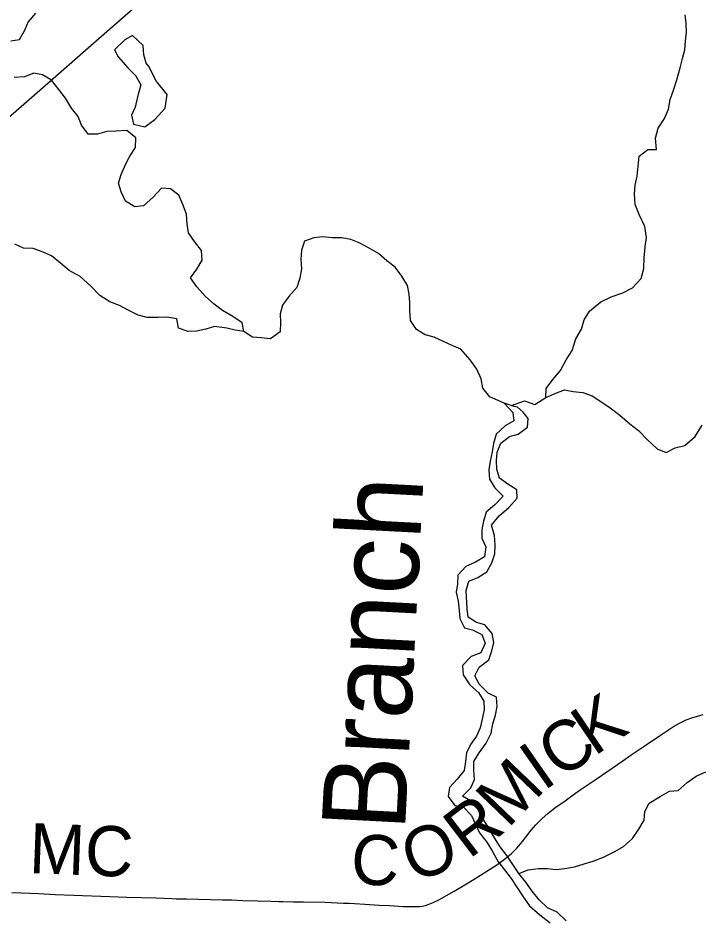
# Model space of a CAD drawing. Extents: x 0 to 34, y 0 to 22.
# Drawn here: x 17.787 to 18.56, y 13.496 to 14.514 of the extents above; entities that cross this region are included whole.
import ezdxf

# ---------------------------------------------------------------- set-up
doc = ezdxf.new("R2010")
doc.units = 0
for name, color, linetype in [('GM_X_County_Road', 7, 'Continuous'), ('GM_X_County_Road_Text', 7, 'Continuous'), ('GM_X_Minor_Lake', 7, 'Continuous'), ('GM_X_Minor_River', 7, 'Continuous'), ('GM_X_Minor_River_Text', 7, 'Continuous'), ('GM_X_Rail_Line', 7, 'Continuous')]:
    doc.layers.add(name, color=color, linetype=linetype)

msp = doc.modelspace()

# ---------------------------------------------------------------- linework, layer by layer
at = {"layer": 'GM_X_County_Road'}
msp.add_lwpolyline([(17.7805, 13.5222), (17.811, 13.5211), (17.8295, 13.5202), (17.8503, 13.5192), (17.8916, 13.5177), (17.9109, 13.5172), (17.9438, 13.5162), (17.9618, 13.5155), (17.9667, 13.5153), (17.9698, 13.5153), (17.9784, 13.515), (18.0193, 13.5141), (18.0302, 13.5139), (18.0426, 13.5134), (18.0594, 13.5127), (18.0743, 13.5124), (18.0836, 13.5122), (18.0879, 13.5121), (18.0996, 13.5119), (18.1114, 13.5117), (18.1357, 13.5113), (18.1568, 13.5104), (18.1636, 13.5101), (18.1865, 13.5088), (18.1971, 13.5081), (18.2088, 13.5074), (18.2243, 13.5066), (18.2286, 13.5063), (18.2323, 13.5063), (18.2357, 13.5063), (18.2397, 13.5064), (18.2429, 13.5066), (18.2462, 13.507), (18.2497, 13.5076), (18.2528, 13.5087), (18.2585, 13.5108), (18.2651, 13.514), (18.2823, 13.5237), (18.2945, 13.5311), (18.305, 13.5376), (18.3193, 13.5464), (18.3318, 13.5545), (18.3408, 13.5611), (18.3473, 13.5667), (18.3534, 13.5728), (18.3599, 13.5803), (18.3649, 13.5866), (18.3699, 13.5929), (18.3751, 13.5991), (18.3821, 13.6063), (18.3886, 13.6121), (18.3965, 13.6183), (18.4082, 13.6265), (18.4173, 13.633), (18.4254, 13.6387), (18.4434, 13.6509), (18.4737, 13.6716), (18.4833, 13.6784), (18.5013, 13.6907), (18.5153, 13.6999), (18.5314, 13.7105), (18.539, 13.7148), (18.5458, 13.7181), (18.5522, 13.7206), (18.5648, 13.7244)], dxfattribs=at)
at = {"layer": 'GM_X_Minor_Lake'}
msp.add_line((17.9437, 14.4434), (17.9363, 14.4589), dxfattribs=at)
msp.add_lwpolyline([(17.9363, 14.4589), (17.9329, 14.463), (17.9301, 14.4725), (17.9293, 14.4831), (17.9174, 14.4944), (17.9087, 14.4897), (17.8967, 14.4782), (17.901, 14.4703), (17.9121, 14.4579), (17.9209, 14.4492), (17.9267, 14.4387), (17.9231, 14.425), (17.9202, 14.4132), (17.9161, 14.404), (17.9185, 14.3938), (17.9314, 14.3909), (17.9427, 14.3994), (17.9543, 14.412), (17.9568, 14.4276), (17.9483, 14.4378), (17.9437, 14.4434)], dxfattribs=at)
at = {"layer": 'GM_X_Minor_River'}
for points in [[(17.7792, 14.4886), (17.789, 14.4902), (17.7946, 14.4998), (17.799, 14.5097), (17.8076, 14.5197)], [(18.3863, 14.0838), (18.3866, 14.094), (18.3944, 14.1044), (18.403, 14.1147), (18.4093, 14.1265), (18.4164, 14.1373), (18.4204, 14.1506), (18.4268, 14.1613), (18.43, 14.172), (18.436, 14.1819), (18.4487, 14.1923), (18.4604, 14.1981), (18.4736, 14.2025), (18.4849, 14.2083), (18.4947, 14.2187), (18.4976, 14.2301), (18.4978, 14.2422), (18.4992, 14.2548), (18.5006, 14.2654), (18.4989, 14.2779), (18.4923, 14.2915), (18.4876, 14.3029), (18.4871, 14.315), (18.4878, 14.3249), (18.4899, 14.3348), (18.4913, 14.3462), (18.4923, 14.3576), (18.5021, 14.3653), (18.5119, 14.3654), (18.5107, 14.3779), (18.5139, 14.3894), (18.521, 14.4004), (18.5254, 14.4111), (18.5276, 14.4218), (18.5309, 14.4313), (18.5349, 14.4443), (18.5389, 14.458), (18.5414, 14.4683), (18.544, 14.4782), (18.545, 14.488), (18.546, 14.4983), (18.5455, 14.5086), (18.5443, 14.518)], [(18.0435, 14.1587), (18.0419, 14.1686), (18.0312, 14.1757), (18.0194, 14.1824), (18.0098, 14.1898), (18.0003, 14.1985), (17.9903, 14.2093), (17.983, 14.2195), (17.9904, 14.2295), (17.9964, 14.2398), (17.9955, 14.2508), (17.9878, 14.261), (17.9809, 14.2707), (17.9793, 14.2806), (17.9784, 14.292), (17.9745, 14.3029), (17.9698, 14.3135), (17.9603, 14.3206), (17.9504, 14.3213), (17.9407, 14.3113), (17.9298, 14.3013), (17.92, 14.3), (17.9093, 14.3067), (17.9046, 14.3173), (17.9015, 14.3271), (17.9044, 14.3367), (17.9092, 14.3481), (17.9144, 14.3577), (17.9207, 14.3676), (17.921, 14.3786), (17.911, 14.3869), (17.8985, 14.3859), (17.8883, 14.3855), (17.8774, 14.3827), (17.8671, 14.3825), (17.8595, 14.3927), (17.8556, 14.4025), (17.8479, 14.4123), (17.8413, 14.4236), (17.8336, 14.4334), (17.8255, 14.4439), (17.8153, 14.4499), (17.8054, 14.4517), (17.7948, 14.4478), (17.7831, 14.4469)], [(18.3391, 14.0775), (18.3227, 14.0845), (18.315, 14.0943), (18.313, 14.1049), (18.308, 14.1162), (18.3006, 14.1268), (18.2899, 14.1388), (18.28, 14.1429), (18.2701, 14.1473), (18.2595, 14.1525), (18.2496, 14.1551), (18.2397, 14.161), (18.2327, 14.1712), (18.2319, 14.1822), (18.2321, 14.1917), (18.2313, 14.2012), (18.2293, 14.211), (18.2231, 14.2216), (18.2154, 14.2317), (18.2058, 14.2388), (18.1963, 14.2471), (18.186, 14.2534), (18.1746, 14.2593), (18.165, 14.263), (18.1548, 14.2652), (18.1438, 14.2651), (18.1332, 14.2661), (18.123, 14.2652), (18.1124, 14.2613), (18.1091, 14.251), (18.1085, 14.2403), (18.109, 14.2297), (18.1072, 14.2191), (18.1039, 14.2088), (18.0949, 14.1984), (18.0875, 14.1888), (18.0849, 14.1789), (18.0854, 14.1691), (18.0848, 14.1584), (18.0739, 14.1503), (18.0633, 14.1514), (18.0534, 14.1524), (18.0435, 14.1587), (18.034, 14.1601), (18.0245, 14.1627), (18.0105, 14.1644), (18.0007, 14.1613), (17.9901, 14.1592), (17.9803, 14.1587), (17.9696, 14.1624), (17.9676, 14.173), (17.9562, 14.1752), (17.9464, 14.1747), (17.9339, 14.1745), (17.9236, 14.1771), (17.9122, 14.183), (17.9027, 14.1882), (17.8916, 14.1923), (17.8802, 14.1997), (17.8699, 14.2102), (17.858, 14.2211), (17.8454, 14.2278), (17.8355, 14.2364), (17.8252, 14.2446), (17.8141, 14.2494), (17.8046, 14.2531), (17.7936, 14.2534), (17.7837, 14.2578)], [(18.3473, 14.0748), (18.3622, 14.0801), (18.3739, 14.076), (18.3863, 14.0838), (18.3977, 14.0888), (18.4075, 14.0927), (18.4173, 14.0906), (18.4283, 14.0896), (18.439, 14.0859), (18.4489, 14.0792), (18.4592, 14.0721), (18.4703, 14.0639), (18.4817, 14.0541), (18.4917, 14.0466), (18.5016, 14.0357), (18.5127, 14.0256), (18.523, 14.0216), (18.5332, 14.0266), (18.5441, 14.0294), (18.5558, 14.0398), (18.5639, 14.0524)], [(18.4093, 13.4902), (18.3993, 13.5), (18.3883, 13.5051), (18.3787, 13.5141), (18.3707, 13.5239), (18.3637, 13.5341), (18.3557, 13.5439), (18.3491, 13.5541), (18.3422, 13.5642), (18.3345, 13.574), (18.3283, 13.5842), (18.3214, 13.5959), (18.3152, 13.6057), (18.3113, 13.6155), (18.3029, 13.6253), (18.2918, 13.6316), (18.3012, 13.6412), (18.3053, 13.6507), (18.3048, 13.661), (18.3046, 13.6709), (18.3106, 13.6808), (18.3188, 13.6919), (18.3244, 13.703), (18.3261, 13.7136), (18.3294, 13.7235), (18.3312, 13.7334), (18.3303, 13.7441), (18.3208, 13.7485), (18.3112, 13.7583), (18.3058, 13.7681), (18.3106, 13.778), (18.3215, 13.7861), (18.3252, 13.7964), (18.3274, 13.8059), (18.3254, 13.8161), (18.3173, 13.8259), (18.3078, 13.8285), (18.2983, 13.8348), (18.297, 13.8443), (18.296, 13.8648), (18.2989, 13.8754), (18.3091, 13.8797), (18.3196, 13.8863), (18.3252, 13.8962), (18.3285, 13.9065), (18.3288, 13.9168), (18.3283, 13.9274), (18.3247, 13.9391), (18.3333, 13.9495), (18.3442, 13.9591), (18.3539, 13.9695), (18.3534, 13.979), (18.3431, 13.9857), (18.3336, 13.9924), (18.3308, 14.0026), (18.3303, 14.0125), (18.331, 14.022), (18.3354, 14.0319), (18.3452, 14.0396), (18.355, 14.0424), (18.3655, 14.0501), (18.3662, 14.06), (18.3606, 14.0673), (18.3541, 14.0731), (18.3506, 14.0737), (18.3391, 14.0775), (18.349, 14.067), (18.3499, 14.0575), (18.3401, 14.0517), (18.33, 14.0421), (18.3271, 14.0318), (18.3253, 14.0223), (18.3232, 14.0116), (18.3218, 14.0014), (18.3226, 13.9911), (18.3284, 13.9813), (18.338, 13.972), (18.3283, 13.9616), (18.3185, 13.9539), (18.3156, 13.9436), (18.3138, 13.9341), (18.3139, 13.9242), (18.3182, 13.9144), (18.3168, 13.903), (18.3066, 13.8972), (18.2957, 13.8921), (18.2864, 13.8825), (18.2861, 13.8726), (18.2847, 13.8631), (18.2867, 13.8529), (18.2879, 13.8427), (18.2888, 13.8332), (18.2939, 13.8226), (18.3033, 13.8204), (18.3136, 13.8149), (18.3175, 13.805), (18.3127, 13.7943), (18.3018, 13.79), (18.2917, 13.7797), (18.2926, 13.7691)], [(18.2926, 13.7691), (18.3003, 13.7578), (18.3098, 13.7491), (18.316, 13.7393), (18.3165, 13.7298), (18.3143, 13.7188), (18.3118, 13.7093), (18.3077, 13.6997), (18.301, 13.6902), (18.2962, 13.6806), (18.2952, 13.6711), (18.2938, 13.6609), (18.2856, 13.6509), (18.277, 13.6413), (18.2755, 13.6314), (18.2832, 13.6212), (18.2927, 13.6195), (18.3019, 13.6097), (18.3066, 13.5999), (18.3112, 13.5901), (18.3193, 13.5795), (18.3255, 13.5697), (18.332, 13.558), (18.3394, 13.5479), (18.347, 13.5381), (18.3536, 13.5283), (18.3605, 13.5174), (18.3678, 13.5072), (18.3797, 13.4971), (18.3912, 13.4881)], [(18.3557, 13.5439), (18.3662, 13.5482), (18.378, 13.5495), (18.3882, 13.5496), (18.398, 13.5485), (18.4079, 13.5494), (18.4188, 13.5514), (18.4298, 13.555), (18.44, 13.5578), (18.4517, 13.5625), (18.4645, 13.5687), (18.4746, 13.5745), (18.4848, 13.5837), (18.4918, 13.5941), (18.4978, 13.6044), (18.4988, 13.6143), (18.5036, 13.6238), (18.516, 13.6312), (18.5266, 13.6374), (18.5364, 13.6379), (18.5469, 13.6471), (18.5571, 13.6544), (18.568, 13.6591)]]:
    msp.add_lwpolyline(points, dxfattribs=at)
at = {"layer": 'GM_X_Rail_Line'}
msp.add_lwpolyline([(17.7547, 14.3825), (17.8212, 14.4406), (17.879, 14.4912), (17.939, 14.5439)], dxfattribs=at)

# ---------------------------------------------------------------- texts
at = {"layer": 'GM_X_County_Road_Text'}
for s, height, rotation, p in [('K', 0.0568, 34.1689, (18.4412, 13.6762)), ('C', 0.0568, 34.2508, (18.4027, 13.65)), ('I', 0.0568, 35.0086, (18.3837, 13.6367)), ('M', 0.0568, 46.1898, (18.3433, 13.5941)), ('R', 0.0568, 37.3717, (18.2991, 13.5594)), ('MC', 0.05682, 357.8134, (17.7992, 13.5444)), ('O', 0.0568, 20.1469, (18.2358, 13.5332)), ('C', 0.0568, 356.2231, (18.1638, 13.5327))]:
    msp.add_text(s, height=height, rotation=rotation, dxfattribs=at).set_placement(p)
at = {"layer": 'GM_X_Minor_River_Text'}
msp.add_text('Branch', height=0.09473, rotation=86.9762, dxfattribs=at).set_placement((18.2264, 13.5911))

doc.saveas('drawing.dxf')
